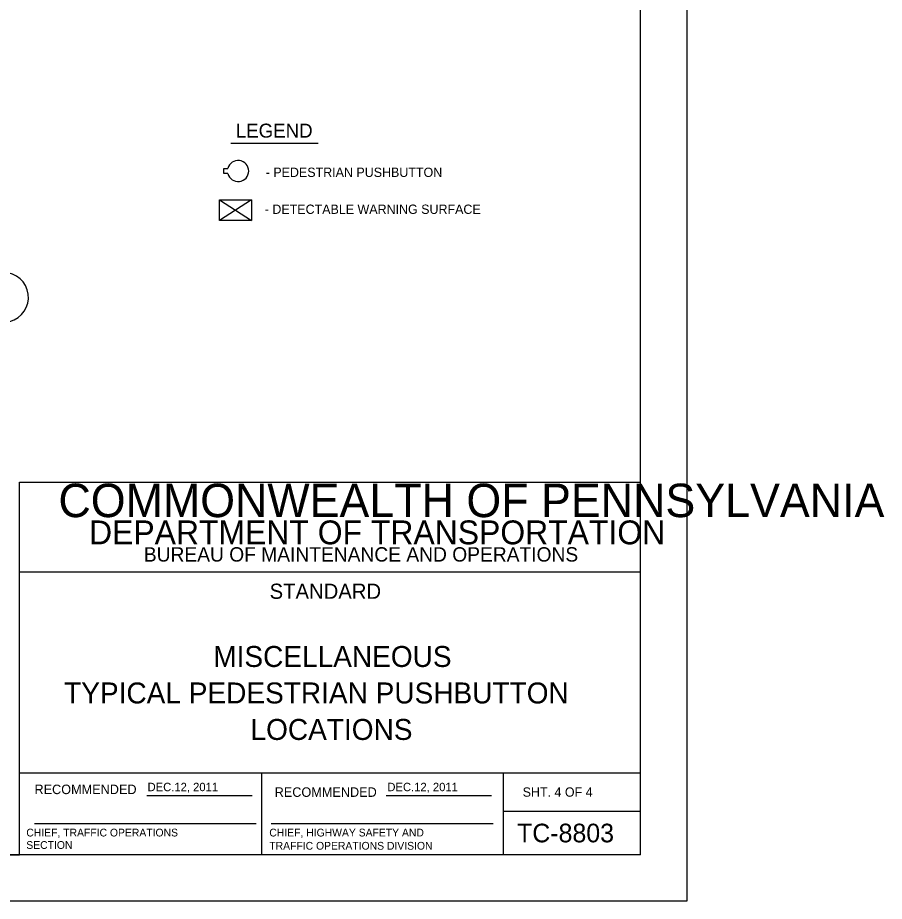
# Model space of a CAD drawing. Extents: x 36 to 940, y -1166 to 1210.
# Drawn here: x 661.3 to 940.4, y -1165.8 to -881.2 of the extents above; entities that cross this region are included whole.
import ezdxf

# ---------------------------------------------------------------- set-up
doc = ezdxf.new("R2010")
doc.units = 0
for name, color, linetype in [('1', 7, 'Continuous'), ('2', 7, 'Continuous'), ('4', 7, 'Continuous'), ('Default', 7, 'Continuous'), ('PLT-BNDY', 7, 'Continuous')]:
    doc.layers.add(name, color=color, linetype=linetype)

msp = doc.modelspace()

# ---------------------------------------------------------------- linework, layer by layer
at = {"layer": '1'}
for p, q in [((861.86, -1150.83), (861.86, -586.83)), ((661.86, -1150.83), (661.86, -1030.83)), ((661.86, -1030.83), (861.86, -1030.83)), ((861.86, -1059.83), (661.86, -1059.83)), ((661.86, -1124.45), (861.86, -1124.45)), ((739.86, -1124.45), (739.86, -1150.83)), ((817.73, -1150.83), (817.73, -1124.45)), ((702.9, -1131.8), (736.82, -1131.8)), ((779.99, -1131.8), (813.91, -1131.8)), ((817.73, -1136.83), (861.86, -1136.83)), ((666.74, -1140.79), (738.07, -1140.79)), ((742.95, -1140.79), (814.41, -1140.79)), ((861.86, -1150.83), (75.86, -1150.83)), ((75.86, -1150.83), (661.86, -1150.83))]:
    msp.add_line(p, q, dxfattribs=at)
at = {"layer": '2'}
for p, q in [((758.08, -921.75), (730.01, -921.75)), ((727.72, -931.46), (727.72, -929.8)), ((727.72, -929.8), (729.02, -929.8)), ((729.02, -931.46), (727.72, -931.46)), ((726.35, -939.94), (736.6, -946.57)), ((736.6, -939.94), (726.35, -946.57))]:
    msp.add_line(p, q, dxfattribs=at)
msp.add_lwpolyline([(726.35, -939.94), (736.6, -939.94), (736.6, -946.57), (726.35, -946.57)], close=True, dxfattribs=at)
msp.add_arc((732.31, -930.63), 3.4, 194.1014, 165.8986, dxfattribs=at)
at = {"layer": 'Default'}
msp.add_arc((656.79, -971.32), 8, 284.7063, 90, dxfattribs=at)
at = {"layer": 'PLT-BNDY'}
msp.add_lwpolyline([(35.86, -571.83), (876.86, -571.83), (876.86, -1165.83), (35.86, -1165.83)], close=True, dxfattribs=at)

# ---------------------------------------------------------------- texts
at = {"layer": '1'}
for s, height, p in [('COMMONWEALTH OF PENNSYLVANIA', 10.7828, (674.45, -1042.1)), ('DEPARTMENT OF TRANSPORTATION', 7.6837, (684.31, -1050.85)), ('BUREAU OF MAINTENANCE AND OPERATIONS', 4.6253, (701.95, -1056.41)), ('MISCELLANEOUS', 6.75, (724.3, -1090.35)), ('TYPICAL PEDESTRIAN PUSHBUTTON', 6.75, (676.28, -1102.1)), ('LOCATIONS', 6.75, (736.3, -1113.85)), ('RECOMMENDED', 3.0516, (666.73, -1131.3)), ('RECOMMENDED', 3.0516, (744.08, -1132.18)), ('SHT. 4 OF 4', 3, (823.94, -1132.14)), ('TC-8803', 6, (822.14, -1146.83))]:
    msp.add_text(s, height=height, dxfattribs=at).set_placement(p)
at = {"layer": '2'}
for s, height, p in [('LEGEND', 4.5, (731.56, -919.88)), ('- PEDESTRIAN PUSHBUTTON', 3, (741.2, -932.54)), ('- DETECTABLE WARNING SURFACE', 3, (740.89, -944.44)), ('DEC.12, 2011', 2.7032, (703.15, -1130.36))]:
    msp.add_text(s, height=height, dxfattribs=at).set_placement(p)
msp.add_text('DEC.12, 2011', height=2.7032, rotation=360, dxfattribs=at).set_placement((780.37, -1130.36))
at = {"layer": '4'}
msp.add_text('STANDARD', height=4.881, rotation=360, dxfattribs=at).set_placement((742.45, -1068.41))
at = {"layer": 'Default'}
for s, p in [('CHIEF, TRAFFIC OPERATIONS', (664.1, -1144.94)), ('CHIEF, HIGHWAY SAFETY AND', (742.35, -1144.94)), ('SECTION', (664.1, -1148.94)), ('TRAFFIC OPERATIONS DIVISION', (742.35, -1149.19))]:
    msp.add_text(s, height=2.5, dxfattribs=at).set_placement(p)

doc.saveas('drawing.dxf')
